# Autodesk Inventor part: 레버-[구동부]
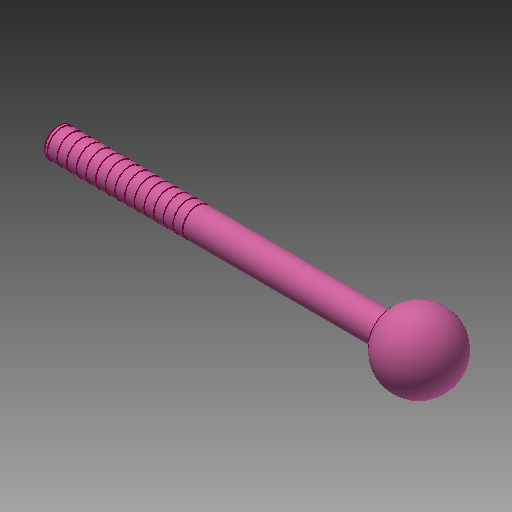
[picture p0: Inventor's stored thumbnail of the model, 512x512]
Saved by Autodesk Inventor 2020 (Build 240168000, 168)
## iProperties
Created: 2015-12
Part Number: 레버-[구동부]
Material: 스테인리스강
Document SubType Name: Modeling
Designer: mduedu
Density: 8.08 g/cm^3
Mass: 29.6046 g
Surface Area: 20.4663 cm^2
Volume: 3.66393 cm^3
Appearance: 분홍색
Author: mduedu
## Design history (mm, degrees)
sketch "스케치1"
  geometry: C1 r 3 at (0, 0); 1 further point
  constraints: 1 centre point, 1 coincident
  dimensions: "d0" = 6 diameter of C1
extrude "돌출1" new body sketch "스케치1" distance "d1" = 75; taper "d2" = 0 deg
sketch "스케치2"
  geometry: L1 (7.5, 0)-(-6, 0); L2 (-6, 4.5)-(-6, 0); A1 r 7.5 centre (0, 0) between (7.5, 0) and (-6, 4.5); 2 further points
  constraints: 4 end point, 2 coincident, 2 point on circle, 1 centre point, 1 horizontal, 1 perpendicular, 1 point on line
  dimensions: "d3" = 15 diameter of A1; "d10" = 6 distance from line of L2 point (0, 0)
revolve "회전1" sketch "스케치2" stored, may be unused: angle "d4" = 90 deg
chamfer "모따기1" distance "d7" = 0.5; stored, may be unused: second distance "d8" = 2, angle "d9" = 45 deg
fillet "모깎기2" dims "d11" = 0.3
sketch "스케치4"
  geometry: L1 (-75, -2.5)-(-75, 2.5) reference; L2 (-75, 0)-(0, 0); L3 (-6.3, 3)-(-74.5, 3) reference; L4 (-74, 3)-(-73.9, 3); L5 (-73.9, 3)-(-73.9, 2.9); L6 (-73.9, 2.9)-(-74, 2.9); L7 (-74, 2.9)-(-74, 3)
  constraints: 10 end point, 2 parallel, 2 perpendicular, 1 horizontal, 1 midpoint, 1 point on line
  dimensions: "d17" = 1 distance between parallel lines of L7 L1; "d18" = 0.1 distance of L5.end L6.end; "d19" = 0.1 distance of L4.end L5.end
revolve "회전3" sketch "스케치4" stored, may be unused: angle "d20" = 90 deg
node "솔리드1"
pattern_linear "직사각형 패턴1" dims "d23" = 2
